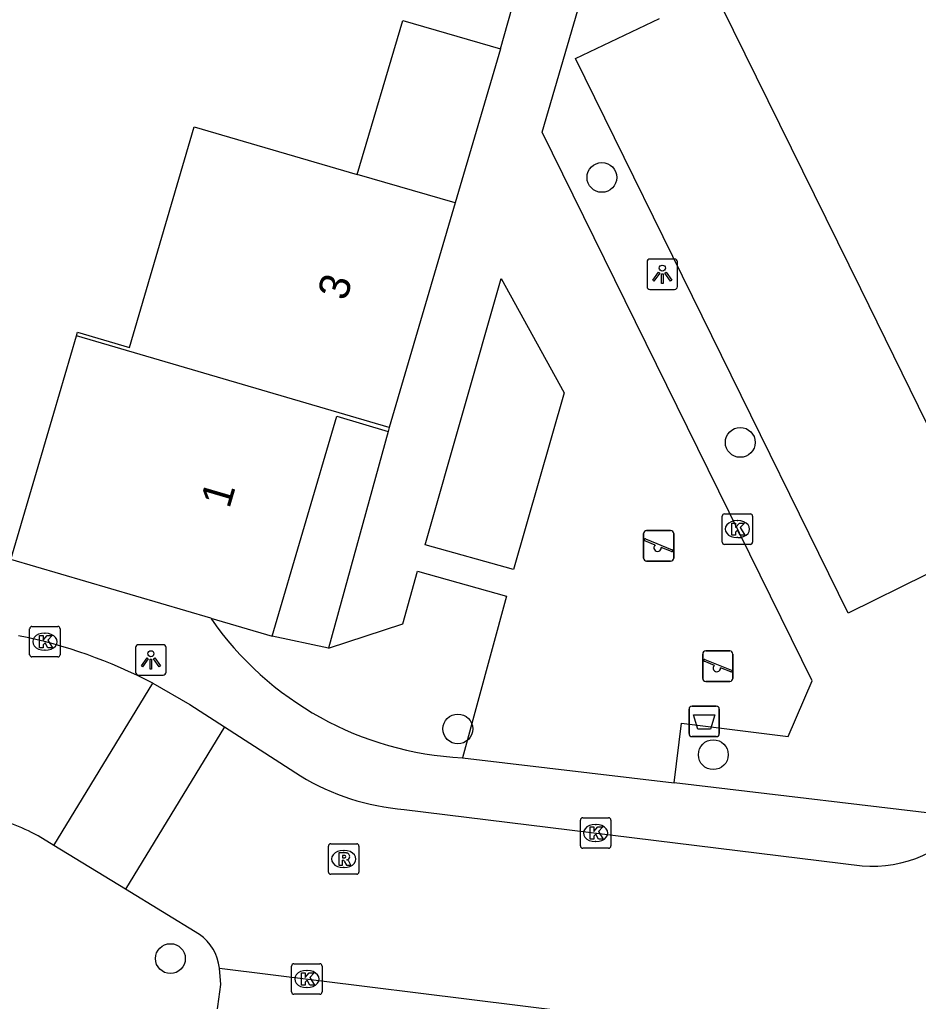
# Model space of a CAD drawing. Extents: x 159718 to 160783, y 383290 to 384030.
# Drawn here: x 160053.1 to 160082.59, y 383379.93 to 383412.13 of the extents above; entities that cross this region are included whole.
import ezdxf

# ---------------------------------------------------------------- set-up
doc = ezdxf.new("R2010")
doc.units = 0
for name, color, linetype in [('IMGEO_Afvalbak', 7, 'Continuous'), ('IMGEO_Boom', 7, 'Continuous'), ('IMGEO_Groenvoorziening', 7, 'Continuous'), ('IMGEO_Kolk', 7, 'Continuous'), ('IMGEO_Lichtpunt', 7, 'Continuous'), ('IMGEO_Pand', 7, 'Continuous'), ('IMGEO_Pand_nummerreeks', 7, 'Continuous'), ('IMGEO_Parkeervlak_open', 7, 'Continuous'), ('IMGEO_Rijbaan_lokaal_open', 7, 'Continuous'), ('IMGEO_Rioolput', 7, 'Continuous'), ('IMGEO_Speelvoorziening', 7, 'Continuous'), ('IMGEO_Voetpad_open', 7, 'Continuous')]:
    doc.layers.add(name, color=color, linetype=linetype)

msp = doc.modelspace()

# ---------------------------------------------------------------- linework, layer by layer
at = {"layer": 'IMGEO_Afvalbak'}
for p, q in [((160075.066, 383388.712), (160075.066, 383389.512)), ((160075.066, 383389.512), (160075.066, 383388.712)), ((160075.166, 383389.612), (160075.956, 383389.612)), ((160075.956, 383389.612), (160075.166, 383389.612)), ((160076.056, 383389.512), (160076.056, 383388.712)), ((160076.056, 383388.712), (160076.056, 383389.512)), ((160075.956, 383388.612), (160075.166, 383388.612)), ((160075.166, 383388.612), (160075.956, 383388.612))]:
    msp.add_line(p, q, dxfattribs=at)
msp.add_lwpolyline([(160075.209, 383389.326), (160075.913, 383389.326), (160075.764, 383388.856), (160075.358, 383388.856), (160075.209, 383389.326)], dxfattribs=at)
for centre, start, end in [((160075.166, 383389.512), 90, 180), ((160075.166, 383389.512), 90, 180), ((160075.956, 383389.512), 0, 90), ((160075.956, 383389.512), 360, 90), ((160075.166, 383388.712), 180, 270), ((160075.166, 383388.712), 180, 270), ((160075.956, 383388.712), 270, 0), ((160075.956, 383388.712), 270, 0)]:
    msp.add_arc(centre, 0.1, start, end, dxfattribs=at)
at = {"layer": 'IMGEO_Boom'}
for centre in [(160072.206, 383406.951), (160076.745, 383398.261), (160067.48, 383388.863), (160075.861, 383388.02), (160058.05, 383381.332)]:
    msp.add_circle(centre, 0.489, dxfattribs=at)
at = {"layer": 'IMGEO_Groenvoorziening'}
msp.add_lwpolyline([(160063.239, 383391.511), (160061.388, 383391.903)], dxfattribs=at)
at = {"layer": 'IMGEO_Kolk'}
for p, q in [((160076.15, 383394.991), (160076.15, 383395.843)), ((160076.225, 383395.917), (160077.077, 383395.917)), ((160076.638, 383395.697), (160076.663, 383395.697)), ((160077.151, 383395.843), (160077.151, 383394.991)), ((160076.661, 383395.137), (160076.636, 383395.137)), ((160077.077, 383394.917), (160076.225, 383394.917)), ((160053.433, 383391.298), (160053.433, 383392.15)), ((160053.508, 383392.224), (160054.36, 383392.224)), ((160054.434, 383392.15), (160054.434, 383391.298)), ((160053.921, 383392.004), (160053.946, 383392.004)), ((160053.944, 383391.444), (160053.919, 383391.444)), ((160054.36, 383391.224), (160053.508, 383391.224)), ((160071.575, 383385.951), (160072.427, 383385.951)), ((160071.5, 383385.025), (160071.5, 383385.877)), ((160071.988, 383385.731), (160072.013, 383385.731)), ((160072.501, 383385.877), (160072.501, 383385.025)), ((160072.011, 383385.171), (160071.986, 383385.171)), ((160072.427, 383384.951), (160071.575, 383384.951)), ((160062.102, 383381.163), (160062.954, 383381.163)), ((160062.027, 383380.237), (160062.027, 383381.089)), ((160062.515, 383380.943), (160062.54, 383380.943)), ((160063.028, 383381.089), (160063.028, 383380.237)), ((160062.954, 383380.163), (160062.102, 383380.163)), ((160062.538, 383380.383), (160062.513, 383380.383))]:
    msp.add_line(p, q, dxfattribs=at)
for points in [[(160076.15, 383394.991), (160076.15, 383395.843)], [(160076.225, 383395.917), (160077.077, 383395.917)], [(160076.471, 383395.617), (160076.594, 383395.617), (160076.594, 383395.466), (160076.724, 383395.617), (160076.888, 383395.617), (160076.742, 383395.466), (160076.895, 383395.217), (160076.743, 383395.217), (160076.658, 383395.381), (160076.594, 383395.314), (160076.594, 383395.217), (160076.471, 383395.217), (160076.471, 383395.617)], [(160077.151, 383395.843), (160077.151, 383394.991)], [(160077.077, 383394.917), (160076.225, 383394.917)], [(160053.433, 383391.298), (160053.433, 383392.15)], [(160053.508, 383392.224), (160054.36, 383392.224)], [(160054.434, 383392.15), (160054.434, 383391.298)], [(160053.754, 383391.924), (160053.877, 383391.924), (160053.877, 383391.773), (160054.007, 383391.924), (160054.171, 383391.924), (160054.025, 383391.773), (160054.178, 383391.524), (160054.026, 383391.524), (160053.941, 383391.688), (160053.877, 383391.621), (160053.877, 383391.524), (160053.754, 383391.524), (160053.754, 383391.924)], [(160054.36, 383391.224), (160053.508, 383391.224)], [(160071.575, 383385.951), (160072.427, 383385.951)], [(160071.5, 383385.025), (160071.5, 383385.877)], [(160071.821, 383385.651), (160071.944, 383385.651), (160071.944, 383385.5), (160072.074, 383385.651), (160072.238, 383385.651), (160072.092, 383385.5), (160072.245, 383385.251), (160072.093, 383385.251), (160072.008, 383385.415), (160071.944, 383385.348), (160071.944, 383385.251), (160071.821, 383385.251), (160071.821, 383385.651)], [(160072.501, 383385.877), (160072.501, 383385.025)], [(160072.427, 383384.951), (160071.575, 383384.951)], [(160062.102, 383381.163), (160062.954, 383381.163)], [(160062.027, 383380.237), (160062.027, 383381.089)], [(160062.348, 383380.863), (160062.471, 383380.863), (160062.471, 383380.712), (160062.601, 383380.863), (160062.765, 383380.863), (160062.619, 383380.712), (160062.772, 383380.463), (160062.62, 383380.463), (160062.535, 383380.627), (160062.471, 383380.56), (160062.471, 383380.463), (160062.348, 383380.463), (160062.348, 383380.863)], [(160063.028, 383381.089), (160063.028, 383380.237)], [(160062.954, 383380.163), (160062.102, 383380.163)]]:
    msp.add_lwpolyline(points, dxfattribs=at)
for centre, start, end in [((160076.227, 383395.841), 91.552, 178.448), ((160076.227, 383395.841), 91.552, 178.448), ((160077.075, 383395.841), 1.552, 88.448), ((160077.075, 383395.841), 1.552, 88.448), ((160076.227, 383394.993), 181.552, 268.448), ((160076.227, 383394.993), 181.552, 268.448), ((160077.075, 383394.993), 271.552, 358.448), ((160077.075, 383394.993), 271.552, 358.448), ((160053.51, 383392.148), 91.552, 178.448), ((160053.51, 383392.148), 91.552, 178.448), ((160054.358, 383392.148), 1.552, 88.448), ((160054.358, 383392.148), 1.552, 88.448), ((160053.51, 383391.3), 181.552, 268.448), ((160053.51, 383391.3), 181.552, 268.448), ((160054.358, 383391.3), 271.552, 358.448), ((160054.358, 383391.3), 271.552, 358.448), ((160071.577, 383385.875), 91.552, 178.448), ((160071.577, 383385.875), 91.552, 178.448), ((160072.425, 383385.875), 1.552, 88.448), ((160072.425, 383385.875), 1.552, 88.448), ((160071.577, 383385.027), 181.552, 268.448), ((160071.577, 383385.027), 181.552, 268.448), ((160072.425, 383385.027), 271.552, 358.448), ((160072.425, 383385.027), 271.552, 358.448), ((160062.104, 383381.087), 91.552, 178.448), ((160062.104, 383381.087), 91.552, 178.448), ((160062.952, 383381.087), 1.552, 88.448), ((160062.952, 383381.087), 1.552, 88.448), ((160062.104, 383380.239), 181.552, 268.448), ((160062.104, 383380.239), 181.552, 268.448), ((160062.952, 383380.239), 271.552, 358.448), ((160062.952, 383380.239), 271.552, 358.448)]:
    msp.add_arc(centre, 0.0765, start, end, dxfattribs=at)
for centre, major_axis, ratio, start_param, end_param in [((160076.637, 383395.417), (-0.387, 0.002), 0.722429, 4.712389, 7.853982), ((160076.662, 383395.417), (-0.39, 0.002), 0.717154, 1.570796, 4.712389), ((160053.92, 383391.724), (-0.387, 0.002), 0.722429, 4.712389, 7.853982), ((160053.945, 383391.724), (-0.39, 0.002), 0.717154, 1.570796, 4.712389), ((160071.987, 383385.451), (-0.387, 0.002), 0.722429, 4.712389, 7.853982), ((160072.012, 383385.451), (-0.39, 0.002), 0.717154, 1.570796, 4.712389), ((160062.514, 383380.663), (-0.387, 0.002), 0.722429, 4.712389, 7.853982), ((160062.539, 383380.663), (-0.39, 0.002), 0.717154, 1.570796, 4.712389)]:
    msp.add_ellipse(centre, major_axis=major_axis, ratio=ratio, start_param=start_param, end_param=end_param, dxfattribs=at)
at = {"layer": 'IMGEO_Lichtpunt'}
for p, q in [((160073.689, 383404.178), (160073.689, 383403.371)), ((160073.689, 383404.178), (160073.689, 383403.371)), ((160074.591, 383404.273), (160073.783, 383404.273)), ((160074.591, 383404.273), (160073.783, 383404.273)), ((160074.685, 383403.371), (160074.685, 383404.178)), ((160074.685, 383403.371), (160074.685, 383404.178)), ((160073.783, 383403.277), (160074.591, 383403.277)), ((160073.783, 383403.277), (160074.591, 383403.277)), ((160056.91, 383391.532), (160056.91, 383390.725)), ((160056.91, 383391.532), (160056.91, 383390.725)), ((160057.812, 383391.627), (160057.004, 383391.627)), ((160057.812, 383391.627), (160057.004, 383391.627)), ((160057.906, 383390.725), (160057.906, 383391.532)), ((160057.906, 383390.725), (160057.906, 383391.532)), ((160057.004, 383390.631), (160057.812, 383390.631)), ((160057.004, 383390.631), (160057.812, 383390.631))]:
    msp.add_line(p, q, dxfattribs=at)
for points in [[(160074.063, 383403.842), (160074.102, 383403.814), (160073.914, 383403.552), (160073.876, 383403.579), (160074.063, 383403.842)], [(160074.165, 383403.794), (160074.212, 383403.794), (160074.212, 383403.472), (160074.165, 383403.472), (160074.165, 383403.794)], [(160074.275, 383403.814), (160074.313, 383403.841), (160074.5, 383403.579), (160074.461, 383403.551), (160074.275, 383403.814)], [(160057.284, 383391.196), (160057.323, 383391.168), (160057.135, 383390.906), (160057.097, 383390.933), (160057.284, 383391.196)], [(160057.386, 383391.148), (160057.433, 383391.148), (160057.433, 383390.826), (160057.386, 383390.826), (160057.386, 383391.148)], [(160057.496, 383391.168), (160057.534, 383391.195), (160057.721, 383390.933), (160057.682, 383390.905), (160057.496, 383391.168)]]:
    msp.add_lwpolyline(points, dxfattribs=at)
for centre in [(160074.188, 383403.976), (160057.409, 383391.33)]:
    msp.add_circle(centre, 0.0994, dxfattribs=at)
for centre, start, end in [((160073.783, 383404.178), 90, 180), ((160073.783, 383404.178), 90, 180), ((160074.591, 383404.178), 0, 90), ((160074.591, 383404.178), 0, 90), ((160073.783, 383403.371), 180, 270), ((160073.783, 383403.371), 180, 270), ((160074.591, 383403.371), 270, 0), ((160074.591, 383403.371), 270, 360), ((160057.004, 383391.532), 90, 180), ((160057.004, 383391.532), 90, 180), ((160057.812, 383391.532), 0, 90), ((160057.812, 383391.532), 0, 90), ((160057.004, 383390.725), 180, 270), ((160057.004, 383390.725), 180, 270), ((160057.812, 383390.725), 270, 0), ((160057.812, 383390.725), 270, 360)]:
    msp.add_arc(centre, 0.0946, start, end, dxfattribs=at)
at = {"layer": 'IMGEO_Pand'}
for points in [[(160064.175, 383407.042), (160065.671, 383412.098), (160068.88, 383411.166)], [(160068.88, 383411.166), (160067.395, 383406.115)], [(160054.969, 383401.761), (160055.002, 383401.874), (160056.707, 383401.373), (160058.832, 383408.61), (160064.175, 383407.042)], [(160067.395, 383406.115), (160064.175, 383407.042)], [(160067.395, 383406.115), (160065.231, 383398.745)], [(160052.814, 383394.42), (160054.222, 383399.218), (160054.969, 383401.761)], [(160065.231, 383398.745), (160054.969, 383401.761)], [(160061.388, 383391.903), (160063.506, 383399.118), (160065.195, 383398.622)], [(160065.231, 383398.745), (160065.195, 383398.622)], [(160059.374, 383392.494), (160052.814, 383394.42)], [(160059.374, 383392.494), (160061.388, 383391.903)]]:
    msp.add_lwpolyline(points, dxfattribs=at)
at = {"layer": 'IMGEO_Parkeervlak_open'}
msp.add_lwpolyline([(160082.854, 383393.924), (160080.28, 383392.663), (160071.343, 383410.855), (160074.095, 383412.165)], dxfattribs=at)
at = {"layer": 'IMGEO_Rijbaan_lokaal_open'}
for points in [[(160074.989, 383414.871), (160080.692, 383403.311), (160085.552, 383393.382)], [(160054.225, 383385.04), (160057.472, 383390.367)], [(160057.472, 383390.367), (160058.685, 383389.668), (160059.828, 383388.929)], [(160059.828, 383388.929), (160056.582, 383383.604)], [(160059.828, 383388.929), (160062.314, 383387.323)], [(160065.722, 383386.224), (160080.742, 383384.372)], [(160054.225, 383385.04), (160053.707, 383385.356)], [(160056.582, 383383.604), (160054.225, 383385.04)], [(160059.007, 383382.126), (160056.582, 383383.604)], [(160059.658, 383381.021), (160082.558, 383378.179)]]:
    msp.add_lwpolyline(points, dxfattribs=at)
for centre, radius, start, end in [((160049.815, 383375.683), 16.56, 62.4604, 78.6935), ((160066.345, 383393.988), 7.789, 238.838, 265.4154), ((160050.817, 383380.156), 5.949, 60.9396, 79.1721), ((160081.049, 383388.595), 4.234, 265.8404, 321.1008), ((160058.08, 383380.836), 1.589, 6.7019, 54.3062)]:
    msp.add_arc(centre, radius, start, end, dxfattribs=at)
at = {"layer": 'IMGEO_Rioolput'}
for p, q in [((160063.235, 383384.172), (160063.235, 383385.024)), ((160063.31, 383385.098), (160064.162, 383385.098)), ((160064.236, 383385.024), (160064.236, 383384.172)), ((160063.723, 383384.878), (160063.748, 383384.878)), ((160064.162, 383384.098), (160063.31, 383384.098)), ((160063.746, 383384.318), (160063.721, 383384.318))]:
    msp.add_line(p, q, dxfattribs=at)
for points in [[(160063.235, 383384.172), (160063.235, 383385.024)], [(160063.31, 383385.098), (160064.162, 383385.098)], [(160064.236, 383385.024), (160064.236, 383384.172)], [(160063.824, 383384.796), (160063.572, 383384.798), (160063.572, 383384.398)], [(160063.75, 383384.717), (160063.696, 383384.717), (160063.696, 383384.636)], [(160063.572, 383384.398), (160063.696, 383384.398), (160063.696, 383384.56), (160063.707, 383384.56)], [(160063.696, 383384.636), (160063.748, 383384.636)], [(160063.754, 383384.531), (160063.825, 383384.398), (160063.965, 383384.398), (160063.9, 383384.524)], [(160064.162, 383384.098), (160063.31, 383384.098)]]:
    msp.add_lwpolyline(points, dxfattribs=at)
for centre, radius, start, end in [((160063.312, 383385.022), 0.0765, 91.552, 178.448), ((160063.312, 383385.022), 0.0765, 91.552, 178.448), ((160064.16, 383385.022), 0.0765, 1.552, 88.448), ((160064.16, 383385.022), 0.0765, 1.552, 88.448), ((160063.756, 383384.621), 0.0964, 77.0061, 93.1865), ((160063.77, 383384.678), 0.0378, 276.6634, 79.6772), ((160063.823, 383384.686), 0.109, 350.3612, 89.416), ((160063.821, 383384.686), 0.112, 277.5842, 350.9817), ((160063.706, 383384.507), 0.0533, 26.0293, 88.6989), ((160063.732, 383384.825), 0.19, 274.7715, 282.9687), ((160063.805, 383384.471), 0.108, 29.5134, 73.7905), ((160063.312, 383384.174), 0.0765, 181.552, 268.448), ((160063.312, 383384.174), 0.0765, 181.552, 268.448), ((160064.16, 383384.174), 0.0765, 271.552, 358.448), ((160064.16, 383384.174), 0.0765, 271.552, 358.448)]:
    msp.add_arc(centre, radius, start, end, dxfattribs=at)
for centre, major_axis, ratio, start_param, end_param in [((160063.722, 383384.598), (-0.387, 0.002), 0.722429, 4.712389, 7.853982), ((160063.747, 383384.598), (-0.39, 0.002), 0.717154, 1.570796, 4.712389)]:
    msp.add_ellipse(centre, major_axis=major_axis, ratio=ratio, start_param=start_param, end_param=end_param, dxfattribs=at)
at = {"layer": 'IMGEO_Speelvoorziening'}
for p, q in [((160073.671, 383395.368), (160074.461, 383395.368)), ((160074.461, 383395.368), (160073.671, 383395.368)), ((160073.571, 383394.468), (160073.571, 383395.268)), ((160073.571, 383395.268), (160073.571, 383394.468)), ((160073.954, 383394.896), (160073.615, 383395.033)), ((160073.64, 383395.093), (160074.516, 383394.74)), ((160074.561, 383395.268), (160074.561, 383394.468)), ((160074.561, 383394.468), (160074.561, 383395.268)), ((160074.492, 383394.68), (160074.152, 383394.817)), ((160074.461, 383394.368), (160073.671, 383394.368)), ((160073.671, 383394.368), (160074.461, 383394.368)), ((160075.613, 383391.42), (160076.403, 383391.42)), ((160076.403, 383391.42), (160075.613, 383391.42)), ((160075.513, 383390.52), (160075.513, 383391.32)), ((160075.513, 383391.32), (160075.513, 383390.52)), ((160075.582, 383391.145), (160076.458, 383390.792)), ((160076.503, 383391.32), (160076.503, 383390.52)), ((160076.503, 383390.52), (160076.503, 383391.32)), ((160075.896, 383390.948), (160075.557, 383391.085)), ((160076.434, 383390.732), (160076.094, 383390.869)), ((160076.403, 383390.42), (160075.613, 383390.42)), ((160075.613, 383390.42), (160076.403, 383390.42))]:
    msp.add_line(p, q, dxfattribs=at)
for centre, radius, start, end in [((160073.671, 383395.268), 0.1, 90, 180), ((160073.671, 383395.268), 0.1, 90, 180), ((160074.461, 383395.268), 0.1, 0, 90), ((160074.461, 383395.268), 0.1, 360, 90), ((160073.628, 383395.063), 0.0327, 68.078, 248.078), ((160074.033, 383394.806), 0.12, 130.9928, 5.1632), ((160074.504, 383394.71), 0.0327, 248.078, 68.078), ((160073.671, 383394.468), 0.1, 180, 270), ((160073.671, 383394.468), 0.1, 180, 270), ((160074.461, 383394.468), 0.1, 270, 0), ((160074.461, 383394.468), 0.1, 270, 0), ((160075.613, 383391.32), 0.1, 90, 180), ((160075.613, 383391.32), 0.1, 90, 180), ((160076.403, 383391.32), 0.1, 0, 90), ((160076.403, 383391.32), 0.1, 360, 90), ((160075.57, 383391.115), 0.0327, 68.078, 248.078), ((160075.975, 383390.858), 0.12, 130.9928, 5.1632), ((160076.446, 383390.762), 0.0327, 248.078, 68.078), ((160075.613, 383390.52), 0.1, 180, 270), ((160075.613, 383390.52), 0.1, 180, 270), ((160076.403, 383390.52), 0.1, 270, 0), ((160076.403, 383390.52), 0.1, 270, 0)]:
    msp.add_arc(centre, radius, start, end, dxfattribs=at)
at = {"layer": 'IMGEO_Voetpad_open'}
for points in [[(160068.88, 383411.166), (160070.627, 383417.38)], [(160074.573, 383387.094), (160074.813, 383389.05), (160078.317, 383388.621), (160079.102, 383390.437), (160070.246, 383408.439), (160072.664, 383416.709)], [(160069.303, 383394.089), (160066.412, 383394.899), (160068.898, 383403.633), (160070.972, 383399.888), (160069.303, 383394.089)], [(160065.195, 383398.622), (160063.239, 383391.511)], [(160063.239, 383391.511), (160065.679, 383392.313), (160066.154, 383394.043), (160069.074, 383393.223), (160067.629, 383387.921)], [(160067.629, 383387.921), (160074.573, 383387.094)], [(160084.344, 383385.936), (160074.573, 383387.094)], [(160079.646, 383373.535), (160059.116, 383376.153), (160059.7, 383380.483), (160059.658, 383381.021)]]:
    msp.add_lwpolyline(points, dxfattribs=at)
msp.add_arc((160068.137, 383398.575), 10.666, 214.7589, 267.2711, dxfattribs=at)

# ---------------------------------------------------------------- texts
at = {"layer": 'IMGEO_Pand_nummerreeks'}
for s, rotation, p in [('3', 73.6374, (160063.818, 383402.875)), ('1', 73.6401, (160059.983, 383396.065))]:
    msp.add_text(s, height=1, rotation=rotation, dxfattribs=at).set_placement(p)

doc.saveas('drawing.dxf')
